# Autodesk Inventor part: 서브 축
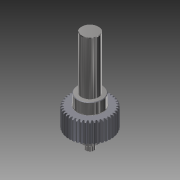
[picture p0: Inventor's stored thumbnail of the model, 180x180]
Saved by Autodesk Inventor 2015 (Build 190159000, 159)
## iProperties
Created: 2014-07
Part Number: 서브 축
Material: 강
Document SubType Name: Modeling
Designer: KYOUNG IL JANG
Categories: <?xml version="1.0" encoding="UTF-16"?> <MemberInstance><Categories><FamilyTemplate><FamilyTemplateParameter ValueType="xs:double" Id="1" ObjectReferenceKey="da
Density: 1 g/cm^3
Appearance: 강철
CustomPartVersion: 1
Company: 한국ATC센터
Author: KYOUNG IL JANG
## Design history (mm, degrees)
sketch "Sketch1"
  geometry: C1 r 21 at (0, 0)
  constraints: 1 centre point
  dimensions: "d0" = 42 diameter of C1 (= da_da)
extrude "Extrusion1" new body sketch "Sketch1" distance "d1" = 20 (= da_b); taper "d2" = 0 deg
workplane "Work Plane2"
feature "피치 지름" dims "d4" = 10, "d5" = 0
workplane "Work Plane8"
workplane "Work Plane9"
chamfer "모따기1" distance "d49" = 1; stored, may be unused: second distance "d50" = 2, angle "d51" = 45 deg
sketch "스케치3"
  geometry: C1 r 12.5 at (0, 0); 1 further point
  constraints: 1 centre point, 1 coincident
  dimensions: "d52" = 25 diameter of C1
extrude "돌출2" join sketch "스케치3" distance "d53" = 11; taper "d54" = 0 deg
sketch "스케치4"
  geometry: C1 r 8.5 at (0, 0); 1 further point
  constraints: 1 centre point, 1 coincident
  dimensions: "d55" = 17 diameter of C1
extrude "돌출3" join sketch "스케치4" distance "d56" = 53; taper "d57" = 0 deg
sketch "스케치5"
  geometry: C1 r 7.5 at (0, 0); 1 further point
  constraints: 1 centre point, 1 coincident
  dimensions: "d62" = 15 diameter of C1
extrude "돌출4" join sketch "스케치5" distance "d63" = 11; taper "d64" = 0 deg
sketch "스케치6"
  geometry: C1 r 4 at (0, 0); 1 further point
  constraints: 1 centre point, 1 coincident
  dimensions: "d65" = 8 diameter of C1
extrude "돌출5" join sketch "스케치6" distance "d66" = 7; taper "d67" = 0 deg
chamfer "모따기2" distance "d58" = 0.5; stored, may be unused: second distance "d59" = 2, angle "d60" = 45 deg
fillet "모깎기1" dims "d61" = 0.5
feature "스퍼 기어" dims "da_b" = 20, "da_d" = 40, "da_aw" = 31, "da_da" = 42, "da_df" = 37.5, "da_dw" = 40, angle "da_beta" = 0 deg, "da_lefttooth" = 0, "da_righttooth" = 0
body "Solid1"
sketch "Sketch2"
  geometry: C1 r 21 at (0, 0) reference; C2 r 20 at (0, 0)
  constraints: 1 centre point, 1 coincident
  dimensions: "d3" = 40 diameter of C2 (= da_dw)
body "Srf1"
other parameters: "d16" = 31 (= da_aw), "d17" = 0, "d34" = 4.5 deg (computed from da_z), "d39" = 0, "d41" = 0, "d43" = 31 (= da_aw), "d46" = 31 (= da_aw), "d47" = 0, "d48" = 0
